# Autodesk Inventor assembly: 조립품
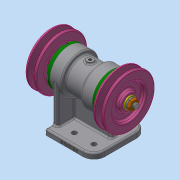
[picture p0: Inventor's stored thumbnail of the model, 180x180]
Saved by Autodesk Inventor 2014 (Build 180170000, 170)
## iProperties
Created: 2020-06
Part Number: 조립품
Document SubType Name: Assembly
Designer: kh
Author: kh
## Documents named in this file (12)
- C:\Users\kh\Desktop\700606V1027\조립품.iam
- C:\Users\kh\Desktop\700606V1027\본체.ipt
- C:\Users\kh\Desktop\700606V1027\베어링 6204.ipt
- C:\Users\kh\Desktop\700606V1027\축.ipt
- C:\Users\kh\Desktop\700606V1027\커버.ipt
- C:\Users\kh\Desktop\700606V1027\오일 실 20 32 5.ipt
- C:\Users\kh\Desktop\700606V1027\Ű 5x5x12.ipt
- C:\Users\kh\Desktop\700606V1027\V-벨트풀리.ipt
- C:\Users\kh\Desktop\700606V1027\평면 와셔 10x21.ipt
- C:\Users\kh\Desktop\700606V1027\스프링 와셔 10.ipt
- C:\Users\kh\Desktop\700606V1027\너트 M10.ipt
- C:\Users\kh\Desktop\700606V1027\볼트 M4.ipt
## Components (4 placed, 2 different names)
1. Ű 5x5x12:1 — Mate:20, Mate:21, Mate:22
2. Ű 5x5x12:2 — Mate:17, Mate:18, Mate:19
3. V-벨트풀리:1 — Mate:24, Flush:2, Angle:2, Mate:27
4. V-벨트풀리:2 — Mate:23, Flush:1, Angle:3, Mate:28
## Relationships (14: Mate 10, Flush 2, Angle 2)
- Mate:17: Ű 5x5x12:2
- Mate:18: Ű 5x5x12:2
- Mate:19: Ű 5x5x12:2
- Mate:20: Ű 5x5x12:1
- Mate:21: Ű 5x5x12:1
- Mate:22: Ű 5x5x12:1
- Mate:23: V-벨트풀리:2
- Mate:24: V-벨트풀리:1
- Flush:1: V-벨트풀리:2
- Flush:2: V-벨트풀리:1
- Angle:2: V-벨트풀리:1
- Angle:3: V-벨트풀리:2
- Mate:27: V-벨트풀리:1
- Mate:28: V-벨트풀리:2
